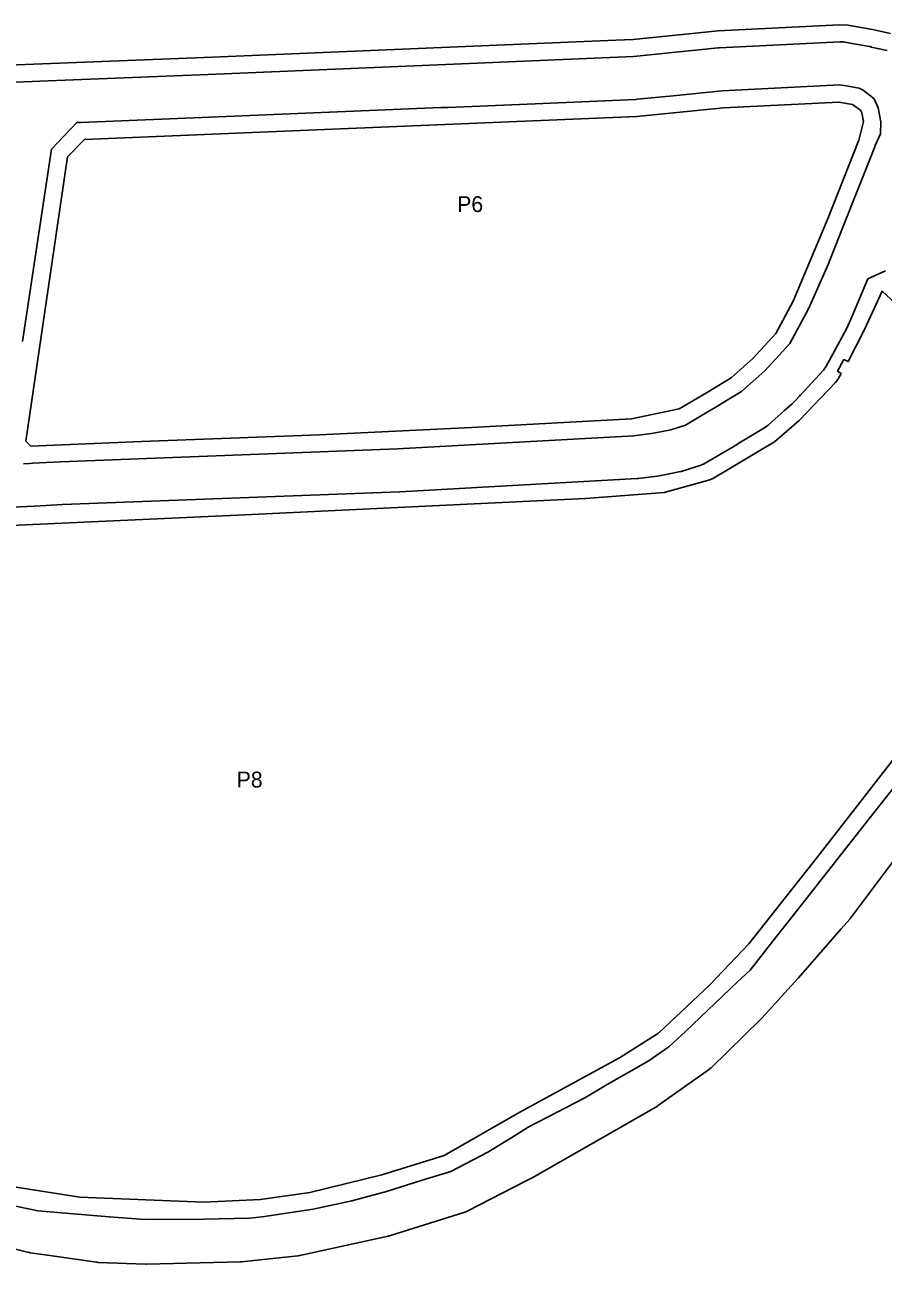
# Model space of a CAD drawing. Extents: x 7428080 to 7432143, y 5545880 to 5549217.
# Drawn here: x 7429139.1 to 7429439.3, y 5546220.5 to 5546654.1 of the extents above; entities that cross this region are included whole.
import ezdxf

# ---------------------------------------------------------------- set-up
doc = ezdxf.new("R2010")
doc.units = 0
for name, color, linetype in [('CZ_L_linie rozgraniczające tereny o różnym przeznaczeniu oraz różnych warunkach ich zabudowy i zagospodarowania', 7, 'Continuous'), ('CZ_L_maksymalne nieprzekraczalne linie zabudowy', 7, 'Continuous'), ('CZ_L_opisy_linie rozgraniczające tereny o różnym przeznaczeniu oraz różnych warunkach ich zabudowy i zagospodarowania', 7, 'Continuous')]:
    doc.layers.add(name, color=color, linetype=linetype)

msp = doc.modelspace()

# ---------------------------------------------------------------- linework, layer by layer
at = {"layer": 'CZ_L_linie rozgraniczające tereny o różnym przeznaczeniu oraz różnych warunkach ich zabudowy i zagospodarowania'}
for p, q in [((7429351.97, 5546642.98), (7429381.62, 5546646)), ((7429381.62, 5546646), (7429382, 5546646.02)), ((7429382, 5546646.02), (7429424.21, 5546648.12)), ((7429424.21, 5546648.12), (7429424.77, 5546648.13)), ((7429424.77, 5546648.13), (7429425.26, 5546648.1)), ((7429425.26, 5546648.1), (7429425.75, 5546648.04)), ((7429425.75, 5546648.04), (7429425.87, 5546648.02)), ((7429425.87, 5546648.02), (7429434.39, 5546646.54)), ((7429434.39, 5546646.54), (7429434.75, 5546646.47)), ((7429434.75, 5546646.47), (7429435.23, 5546646.34)), ((7429435.23, 5546646.34), (7429435.69, 5546646.19)), ((7429435.69, 5546646.19), (7429440.64, 5546645.18)), ((7429286.36, 5546640.22), (7429351.97, 5546642.98)), ((7429144.32, 5546634.43), (7429203.27, 5546636.75)), ((7429203.27, 5546636.75), (7429286.36, 5546640.22)), ((7429122.49, 5546633.57), (7429141.68, 5546634.33)), ((7429141.68, 5546634.33), (7429144.32, 5546634.43)), ((7429382.94, 5546631.05), (7429424.13, 5546633.1)), ((7429424.13, 5546633.1), (7429426.32, 5546632.72)), ((7429426.32, 5546632.72), (7429430.87, 5546631.93)), ((7429353.27, 5546628.04), (7429365.86, 5546629.32)), ((7429365.86, 5546629.32), (7429382.94, 5546631.05)), ((7429430.87, 5546631.93), (7429432.25, 5546631.3)), ((7429432.25, 5546631.3), (7429436.16, 5546628.16)), ((7429436.16, 5546628.16), (7429437.56, 5546625.11)), ((7429203.88, 5546621.77), (7429284.61, 5546625.14)), ((7429284.61, 5546625.14), (7429286.99, 5546625.24)), ((7429286.99, 5546625.24), (7429312.11, 5546626.29)), ((7429312.11, 5546626.29), (7429352.82, 5546628)), ((7429352.82, 5546628), (7429353.27, 5546628.04)), ((7429437.56, 5546625.11), (7429438.48, 5546620.15)), ((7429148.42, 5546610.65), (7429157.28, 5546619.93)), ((7429157.28, 5546619.93), (7429158.66, 5546619.99)), ((7429158.66, 5546619.99), (7429203.86, 5546621.77)), ((7429203.86, 5546621.77), (7429203.87, 5546621.77)), ((7429203.87, 5546621.77), (7429203.88, 5546621.77)), ((7429438.48, 5546620.15), (7429438.38, 5546615.97)), ((7429438.38, 5546615.97), (7429436.47, 5546611.89)), ((7429436.29, 5546611.47), (7429424.92, 5546582.7)), ((7429436.31, 5546611.49), (7429436.29, 5546611.47)), ((7429436.32, 5546611.51), (7429436.31, 5546611.49)), ((7429436.45, 5546611.83), (7429436.32, 5546611.51)), ((7429436.32, 5546611.51), (7429436.32, 5546611.51)), ((7429436.47, 5546611.89), (7429436.45, 5546611.83)), ((7429436.45, 5546611.83), (7429436.45, 5546611.83)), ((7429138.29, 5546543.29), (7429148.42, 5546610.65)), ((7429424.92, 5546582.7), (7429420.02, 5546570.3)), ((7429420.02, 5546570.3), (7429413.16, 5546554.79)), ((7429433.85, 5546565.21), (7429440.07, 5546568.03)), ((7429428.68, 5546552.8), (7429433.85, 5546565.21)), ((7429413.16, 5546554.79), (7429406.61, 5546542.62)), ((7429426.76, 5546548.46), (7429428.68, 5546552.8)), ((7429421.73, 5546539.07), (7429426.51, 5546547.94)), ((7429426.51, 5546547.94), (7429426.54, 5546548.01)), ((7429426.54, 5546548.01), (7429426.55, 5546548.03)), ((7429426.55, 5546548.03), (7429426.68, 5546548.32)), ((7429426.68, 5546548.32), (7429426.73, 5546548.4)), ((7429426.73, 5546548.4), (7429426.76, 5546548.46)), ((7429406.61, 5546542.62), (7429397.85, 5546533.12)), ((7429419.37, 5546534.67), (7429421.73, 5546539.07)), ((7429397.85, 5546533.12), (7429389.69, 5546525.78)), ((7429411.55, 5546525.85), (7429418.28, 5546533.15)), ((7429418.28, 5546533.15), (7429418.4, 5546533.29)), ((7429418.4, 5546533.29), (7429419.27, 5546534.51)), ((7429419.27, 5546534.51), (7429419.31, 5546534.59)), ((7429419.31, 5546534.59), (7429419.37, 5546534.67)), ((7429389.69, 5546525.78), (7429385.29, 5546523.11)), ((7429408.64, 5546522.69), (7429410.01, 5546524.18)), ((7429410.01, 5546524.18), (7429410.41, 5546524.61)), ((7429410.41, 5546524.61), (7429411.55, 5546525.85)), ((7429380.52, 5546520.21), (7429377.13, 5546518.22)), ((7429385.29, 5546523.11), (7429380.52, 5546520.21)), ((7429404.91, 5546519.29), (7429405.75, 5546520.05)), ((7429405.75, 5546520.05), (7429407.42, 5546521.55)), ((7429407.42, 5546521.55), (7429408.14, 5546522.2)), ((7429408.14, 5546522.2), (7429408.18, 5546522.24)), ((7429408.18, 5546522.24), (7429408.19, 5546522.25)), ((7429408.19, 5546522.25), (7429408.59, 5546522.64)), ((7429408.59, 5546522.64), (7429408.61, 5546522.67)), ((7429408.61, 5546522.67), (7429408.64, 5546522.69)), ((7429377.13, 5546518.22), (7429370.12, 5546514.1)), ((7429399.2, 5546514.16), (7429404.91, 5546519.29)), ((7429358.93, 5546511.2), (7429352.09, 5546510.31)), ((7429365.05, 5546512.41), (7429358.93, 5546511.2)), ((7429370.12, 5546514.1), (7429365.05, 5546512.41)), ((7429388.26, 5546507.36), (7429398.08, 5546513.32)), ((7429398.08, 5546513.32), (7429398.15, 5546513.38)), ((7429398.15, 5546513.38), (7429398.25, 5546513.45)), ((7429398.25, 5546513.45), (7429398.66, 5546513.78)), ((7429398.66, 5546513.78), (7429399.02, 5546514.02)), ((7429399.02, 5546514.02), (7429399.13, 5546514.11)), ((7429399.13, 5546514.11), (7429399.2, 5546514.16)), ((7429352.09, 5546510.31), (7429269.46, 5546505.76)), ((7429386.78, 5546506.5), (7429387.53, 5546506.93)), ((7429387.53, 5546506.93), (7429388.17, 5546507.31)), ((7429388.17, 5546507.31), (7429388.18, 5546507.32)), ((7429388.18, 5546507.32), (7429388.19, 5546507.33)), ((7429388.19, 5546507.33), (7429388.26, 5546507.36)), ((7429269.46, 5546505.76), (7429151.61, 5546501.25)), ((7429377.05, 5546500.77), (7429386.78, 5546506.5)), ((7429140.7, 5546500.67), (7429138.7, 5546500.57)), ((7429141.88, 5546500.74), (7429140.7, 5546500.67)), ((7429151.51, 5546501.24), (7429141.88, 5546500.74)), ((7429151.52, 5546501.24), (7429151.51, 5546501.24)), ((7429151.53, 5546501.24), (7429151.52, 5546501.24)), ((7429151.57, 5546501.24), (7429151.53, 5546501.24)), ((7429151.61, 5546501.25), (7429151.57, 5546501.24)), ((7429369.14, 5546497.98), (7429369.25, 5546498.01)), ((7429369.25, 5546498.01), (7429369.34, 5546498.03)), ((7429369.34, 5546498.03), (7429375.62, 5546500.12)), ((7429375.62, 5546500.12), (7429375.68, 5546500.15)), ((7429375.68, 5546500.15), (7429375.69, 5546500.15)), ((7429375.69, 5546500.15), (7429376.32, 5546500.4)), ((7429376.32, 5546500.4), (7429376.38, 5546500.44)), ((7429376.38, 5546500.44), (7429376.46, 5546500.46)), ((7429376.46, 5546500.46), (7429376.98, 5546500.73)), ((7429376.98, 5546500.73), (7429376.99, 5546500.74)), ((7429376.99, 5546500.74), (7429377.05, 5546500.77)), ((7429270.22, 5546490.78), (7429353.19, 5546495.35)), ((7429353.19, 5546495.35), (7429353.21, 5546495.35)), ((7429353.21, 5546495.35), (7429353.24, 5546495.36)), ((7429353.24, 5546495.36), (7429353.25, 5546495.36)), ((7429353.25, 5546495.36), (7429353.67, 5546495.39)), ((7429353.67, 5546495.39), (7429353.68, 5546495.39)), ((7429353.68, 5546495.39), (7429353.74, 5546495.4)), ((7429353.74, 5546495.4), (7429361.11, 5546496.35)), ((7429361.11, 5546496.35), (7429361.19, 5546496.38)), ((7429361.19, 5546496.38), (7429361.28, 5546496.39)), ((7429361.28, 5546496.39), (7429361.49, 5546496.42)), ((7429361.49, 5546496.42), (7429361.52, 5546496.42)), ((7429361.52, 5546496.42), (7429361.6, 5546496.43)), ((7429361.6, 5546496.43), (7429368.43, 5546497.79)), ((7429368.43, 5546497.79), (7429368.52, 5546497.82)), ((7429368.52, 5546497.82), (7429368.6, 5546497.83)), ((7429368.6, 5546497.83), (7429368.92, 5546497.94)), ((7429368.92, 5546497.94), (7429369.14, 5546497.98)), ((7429152.24, 5546486.26), (7429270.1, 5546490.78)), ((7429270.1, 5546490.78), (7429270.16, 5546490.79)), ((7429270.16, 5546490.79), (7429270.2, 5546490.78)), ((7429270.2, 5546490.78), (7429270.21, 5546490.79)), ((7429270.21, 5546490.79), (7429270.22, 5546490.78)), ((7429134.67, 5546485.34), (7429142.51, 5546485.75)), ((7429142.51, 5546485.75), (7429152.24, 5546486.26)), ((7429454.13, 5546401.56), (7429430.79, 5546371.83)), ((7429430.79, 5546371.83), (7429413.73, 5546350.1)), ((7429444.22, 5546363.49), (7429427.8, 5546341.59)), ((7429413.73, 5546350.1), (7429400.73, 5546333.56)), ((7429424.53, 5546337.82), (7429409.6, 5546320.72)), ((7429427.57, 5546341.3), (7429424.53, 5546337.82)), ((7429427.58, 5546341.33), (7429427.57, 5546341.3)), ((7429427.8, 5546341.59), (7429427.58, 5546341.33)), ((7429400.73, 5546333.56), (7429392.71, 5546323.42)), ((7429392.71, 5546323.42), (7429388.36, 5546319.27)), ((7429409.54, 5546320.65), (7429396.87, 5546306.63)), ((7429409.57, 5546320.69), (7429409.54, 5546320.65)), ((7429409.6, 5546320.72), (7429409.57, 5546320.69)), ((7429388.36, 5546319.27), (7429370.14, 5546301.98)), ((7429396.65, 5546306.4), (7429379.08, 5546289.27)), ((7429396.74, 5546306.53), (7429396.65, 5546306.4)), ((7429396.87, 5546306.63), (7429396.74, 5546306.53)), ((7429370.14, 5546301.98), (7429364.37, 5546296.55)), ((7429364.37, 5546296.55), (7429357.09, 5546291.62)), ((7429357.09, 5546291.62), (7429342.79, 5546283.36)), ((7429378.49, 5546288.78), (7429360.73, 5546276.15)), ((7429378.94, 5546289.18), (7429378.49, 5546288.78)), ((7429379.08, 5546289.27), (7429378.94, 5546289.18)), ((7429342.79, 5546283.36), (7429334.91, 5546278.79)), ((7429334.91, 5546278.79), (7429321.89, 5546272.02)), ((7429360.32, 5546275.88), (7429334.7, 5546261.18)), ((7429360.43, 5546275.97), (7429360.32, 5546275.88)), ((7429360.73, 5546276.15), (7429360.43, 5546275.97)), ((7429315.08, 5546268.47), (7429310.9, 5546265.82)), ((7429321.89, 5546272.02), (7429315.08, 5546268.47)), ((7429310.9, 5546265.82), (7429301.01, 5546259.75)), ((7429301.01, 5546259.75), (7429288.12, 5546253)), ((7429334.7, 5546261.18), (7429317.37, 5546251.23)), ((7429288.12, 5546253), (7429278.03, 5546249.98)), ((7429317.17, 5546251.13), (7429316.08, 5546250.57)), ((7429317.2, 5546251.15), (7429317.17, 5546251.13)), ((7429317.37, 5546251.23), (7429317.2, 5546251.15)), ((7429278.03, 5546249.98), (7429265.59, 5546246.01)), ((7429314.39, 5546249.69), (7429293.83, 5546239.06)), ((7429316.08, 5546250.57), (7429314.39, 5546249.69)), ((7429143.67, 5546239.19), (7429127.03, 5546242.77)), ((7429253.49, 5546242.69), (7429239.93, 5546239.76)), ((7429265.59, 5546246.01), (7429253.49, 5546242.69)), ((7429168.61, 5546237.07), (7429143.67, 5546239.19)), ((7429239.93, 5546239.76), (7429222.08, 5546237.16)), ((7429293.02, 5546238.73), (7429266.61, 5546230.51)), ((7429293.64, 5546238.97), (7429293.02, 5546238.73)), ((7429293.73, 5546239.04), (7429293.64, 5546238.97)), ((7429293.83, 5546239.06), (7429293.73, 5546239.04)), ((7429181.23, 5546236.23), (7429168.61, 5546237.07)), ((7429201.7, 5546236.25), (7429181.23, 5546236.23)), ((7429217.73, 5546236.68), (7429201.7, 5546236.25)), ((7429222.08, 5546237.16), (7429217.73, 5546236.68)), ((7429140.5, 5546224.63), (7429120.43, 5546229.64)), ((7429266.2, 5546230.4), (7429235.23, 5546223.58)), ((7429266.43, 5546230.48), (7429266.2, 5546230.4)), ((7429266.61, 5546230.51), (7429266.43, 5546230.48)), ((7429140.69, 5546224.61), (7429140.5, 5546224.63)), ((7429141, 5546224.53), (7429140.69, 5546224.61)), ((7429147.04, 5546223.67), (7429141, 5546224.53)), ((7429164.17, 5546221.23), (7429147.04, 5546223.67)), ((7429164.55, 5546221.21), (7429164.17, 5546221.23)), ((7429164.68, 5546221.19), (7429164.55, 5546221.21)), ((7429181.39, 5546220.54), (7429164.68, 5546221.19)), ((7429181.69, 5546220.54), (7429181.39, 5546220.54)), ((7429181.71, 5546220.54), (7429181.69, 5546220.54)), ((7429214.51, 5546221.34), (7429181.71, 5546220.54)), ((7429214.73, 5546221.39), (7429214.51, 5546221.34)), ((7429214.92, 5546221.37), (7429214.73, 5546221.39)), ((7429217.05, 5546221.6), (7429214.92, 5546221.37)), ((7429222.46, 5546222.18), (7429217.05, 5546221.6)), ((7429234.69, 5546223.49), (7429222.46, 5546222.18)), ((7429234.82, 5546223.53), (7429234.69, 5546223.49)), ((7429235.23, 5546223.58), (7429234.82, 5546223.53))]:
    msp.add_line(p, q, dxfattribs=at)
at = {"layer": 'CZ_L_maksymalne nieprzekraczalne linie zabudowy'}
for points in [[(7428868.34, 5546607.92), (7428896.21, 5546609.11), (7428910.11, 5546611.18), (7428935.35, 5546617.31), (7428972.44, 5546627.97), (7428985.35, 5546631.86), (7428987.81, 5546632.35), (7429057.59, 5546637.52), (7429124.34, 5546639.65), (7429204.75, 5546642.82), (7429345.79, 5546648.72), (7429351.88, 5546649), (7429381.55, 5546652.01), (7429423.97, 5546654.12), (7429426.89, 5546653.93), (7429435.55, 5546652.43), (7429441.84, 5546651.07)], [(7429242.12, 5546510.72), (7429295.28, 5546513.19), (7429351.3, 5546516.27), (7429367.93, 5546519.77), (7429377.44, 5546525.37), (7429386.1, 5546530.62), (7429393.63, 5546537.39), (7429401.68, 5546546.13), (7429407.74, 5546557.38), (7429420.01, 5546586.6), (7429430.74, 5546613.71), (7429432.34, 5546620.32), (7429431.79, 5546623.29), (7429431.38, 5546624.2), (7429428.5, 5546626.25), (7429423.76, 5546627.07), (7429383.39, 5546625.07), (7429353.07, 5546622.01), (7429159.95, 5546614.04), (7429154.08, 5546607.89), (7429139.5, 5546508.49), (7429141.2, 5546506.68), (7429179.87, 5546508.33), (7429242.12, 5546510.72)], [(7429478.18, 5546524.51), (7429438.86, 5546560.89), (7429432.75, 5546547.55), (7429427.04, 5546536.28), (7429425.51, 5546536.97), (7429423.34, 5546532.89), (7429424.6, 5546532.08), (7429423.4, 5546530.02), (7429422.61, 5546529), (7429409.89, 5546515.7), (7429401.28, 5546508.25), (7429379.92, 5546495.5), (7429378.67, 5546494.99), (7429362.63, 5546490.52), (7429335.13, 5546488.35), (7429216.04, 5546482.7), (7428985.81, 5546472.18)], [(7429201.69, 5546242.25), (7429221.51, 5546243.14), (7429238.79, 5546245.65), (7429263.98, 5546251.8), (7429285.71, 5546258.53), (7429312.21, 5546273.73), (7429347.03, 5546292.74), (7429360.67, 5546301.32), (7429378.61, 5546318.3), (7429392.32, 5546332.59), (7429416.4, 5546363.22), (7429453.91, 5546411.45)], [(7429128.46, 5546248.62), (7429158.31, 5546243.98), (7429201.69, 5546242.25)]]:
    msp.add_lwpolyline(points, dxfattribs=at)

# ---------------------------------------------------------------- texts
at = {"layer": 'CZ_L_opisy_linie rozgraniczające tereny o różnym przeznaczeniu oraz różnych warunkach ich zabudowy i zagospodarowania'}
for s, p in [('P6', (7429290.3, 5546588.61)), ('P8', (7429213.2, 5546387.31))]:
    msp.add_text(s, height=5.549, dxfattribs=at).set_placement(p)

doc.saveas('drawing.dxf')
